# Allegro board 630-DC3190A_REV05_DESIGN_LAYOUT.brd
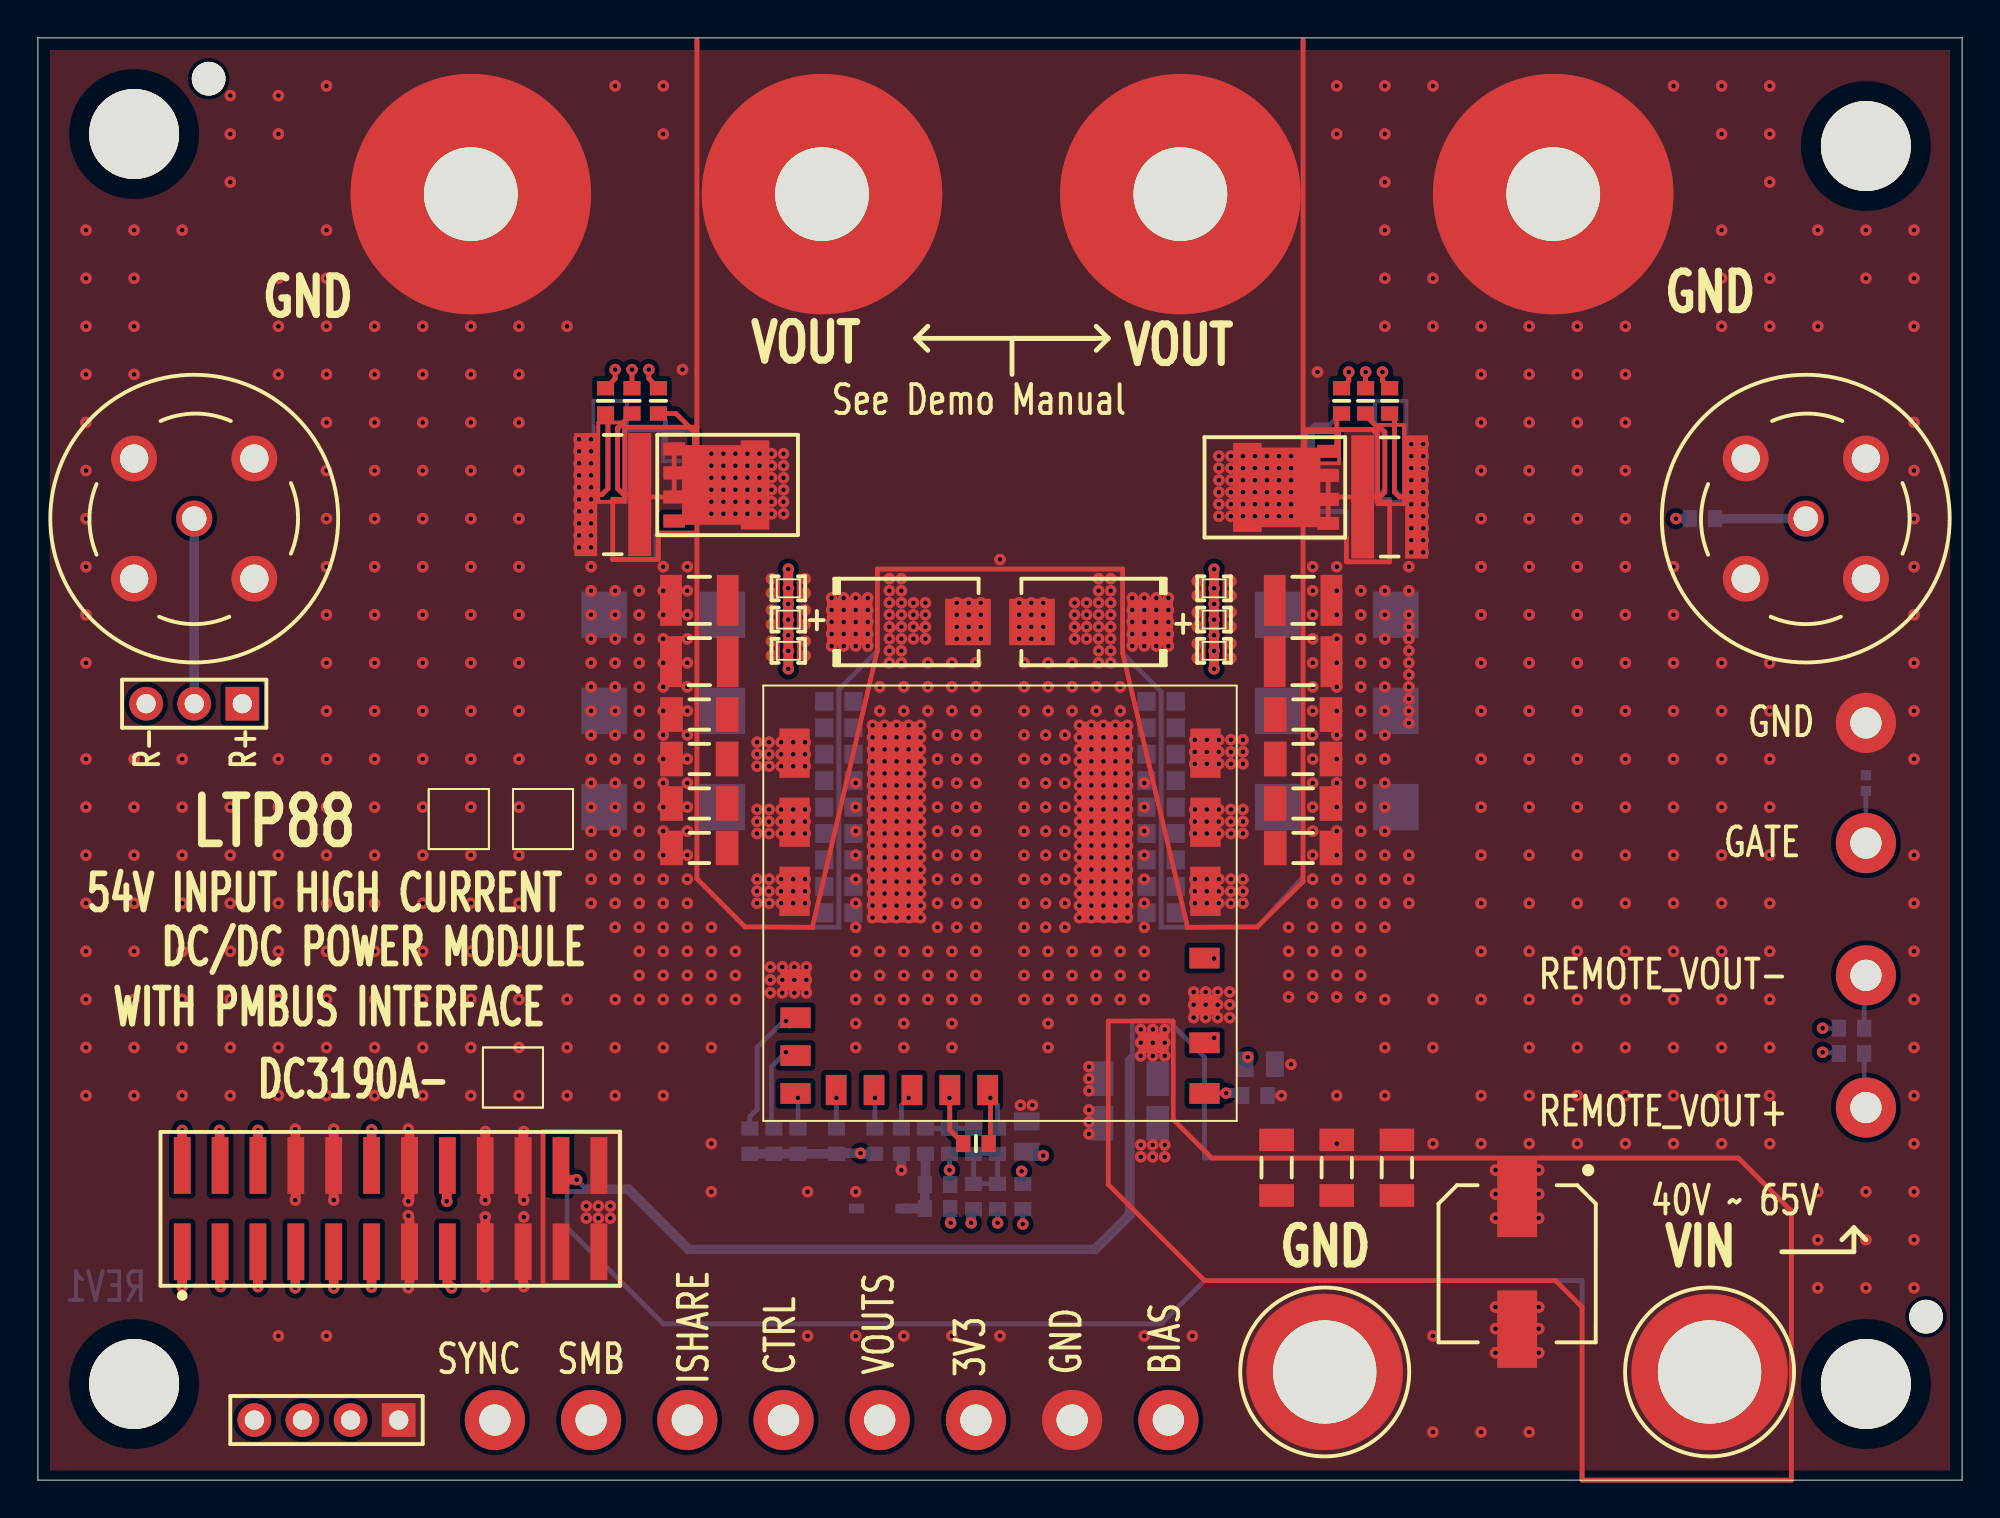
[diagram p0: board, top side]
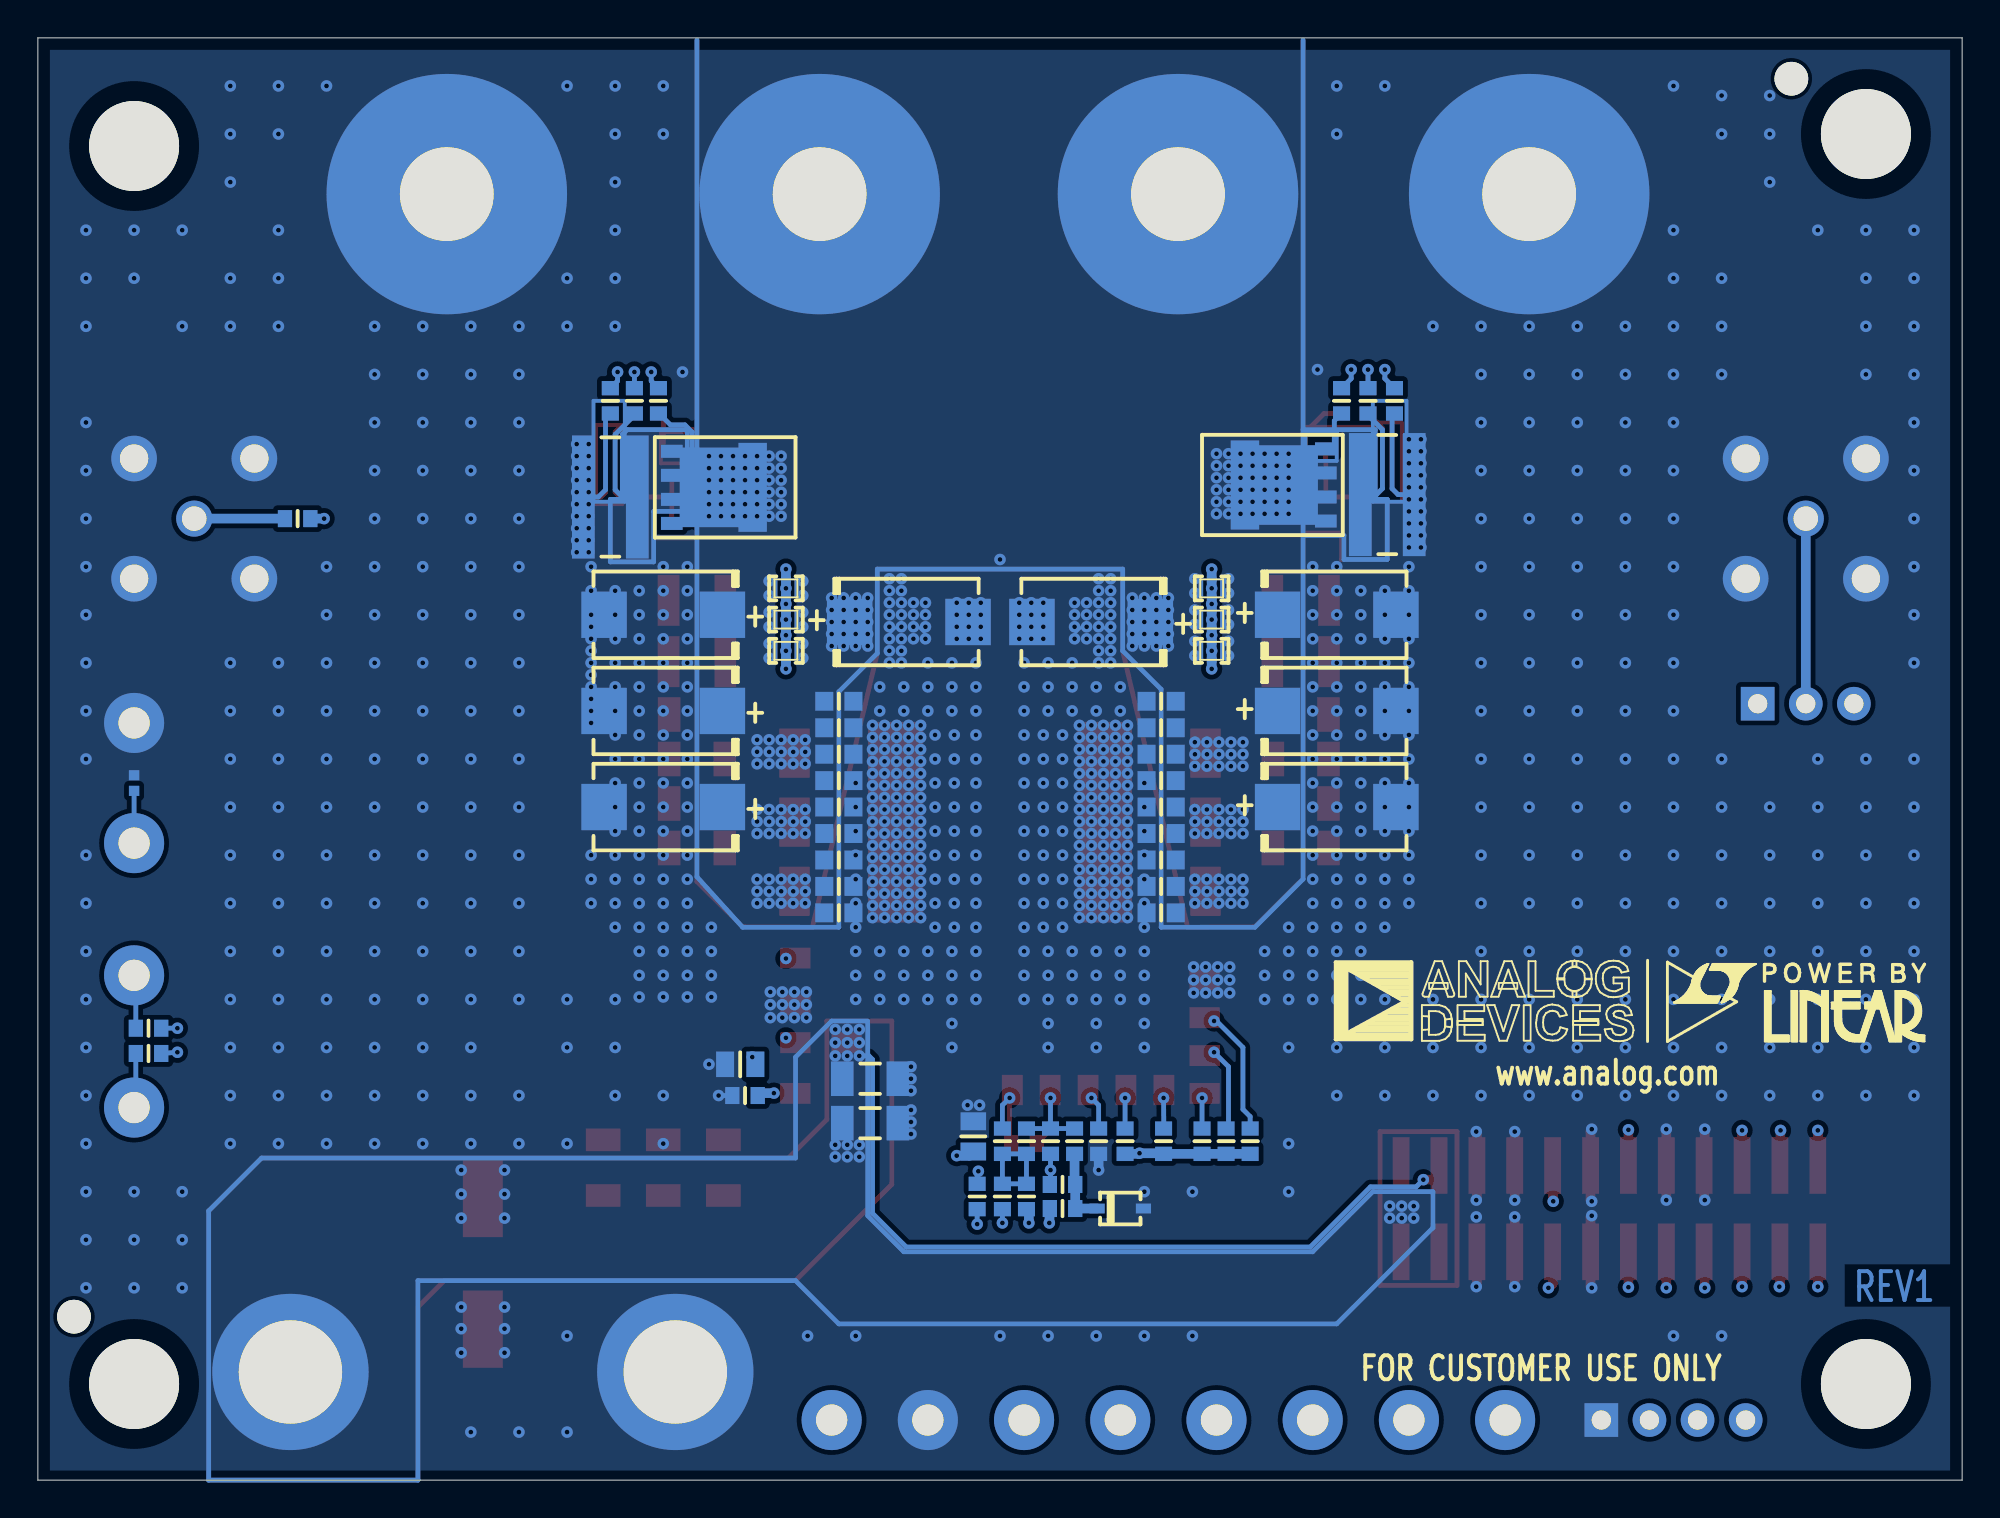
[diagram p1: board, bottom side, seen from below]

Outline 101.6 x 76.2 mm; copper layers: TOP, LAYER2, LAYER3, LAYER4, LAYER5, LAYER6, LAYER7, BOTTOM. Coordinates in mm from the lower left corner of the outline.
Outline path: 0,76.2 0,0 101.6,0 101.6,76.2 0,76.2

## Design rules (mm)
constraint set DEFAULT: min track width 0.254
nets with their own width: min track width 0.127; nets CTRL GND ISHARE LOADGATE N17349827 N17349858 N17349901 N17354471 N17359340 N17393939 N17425885 N173357071 N173562991 N173563321 N174258781 RSENSE+ RSENSE- SCL SDA SMBALERT SYNC VDD VDDEXT VIN VOUT

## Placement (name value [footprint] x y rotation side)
C5  10uF  [CC0603N]  59.31 41.15 180 bottom
C6  10uF  [CC0603N]  42.29 41.15 0 bottom
C7  10uF  [CC0603N]  59.31 39.75 180 bottom
C8  10uF  [CC0603N]  42.29 39.75 0 bottom
C9  10uF  [CC0603N]  59.31 38.35 180 bottom
C10  10uF  [CC0603N]  42.29 38.35 0 bottom
C11  10uF  [CC0603N]  59.31 36.96 180 bottom
C12  10uF  [CC0603N]  42.29 36.96 0 bottom
C13  10uF  [CC0603N]  59.31 35.56 180 bottom
C14  10uF  [CC0603N]  42.29 35.56 0 bottom
C15  10uF  [CC0603N]  59.31 34.16 180 bottom
C16  10uF  [CC0603N]  42.29 34.16 0 bottom
C17  10uF  [CC0603N]  59.31 32.77 180 bottom
C18  10uF  [CC0603N]  42.29 32.77 0 bottom
C19  10uF  [CC0603N]  59.31 31.37 180 bottom
C20  10uF  [CC0603N]  42.29 31.37 0 bottom
C21  10uF  [CC0603N]  59.31 29.97 180 bottom
C22  10uF  [CC0603N]  42.29 29.97 0 bottom
C23  22uF  [MURATA-NFMJMPC]  62.1 47.12 0 top
C24  22uF  [MURATA-NFMJMPC]  62.1 45.47 0 top
C25  22uF  [MURATA-NFMJMPC]  62.1 43.81 0 top
C26  22uF  [MURATA-NFMJMPC]  62.1 45.47 180 bottom
C27  22uF  [MURATA-NFMJMPC]  62.1 43.81 180 bottom
C28  22uF  [MURATA-NFMJMPC]  62.1 47.12 180 bottom
C29  22uF  [MURATA-NFMJMPC]  39.62 47.12 180 bottom
C30  22uF  [MURATA-NFMJMPC]  39.62 45.47 180 bottom
C31  22uF  [MURATA-NFMJMPC]  39.62 43.81 180 bottom
C32  22uF  [MURATA-NFMJMPC]  39.62 47.12 0 top
C33  22uF  [MURATA-NFMJMPC]  39.62 45.47 0 top
C34  22uF  [MURATA-NFMJMPC]  39.62 43.81 0 top
C45  2.2uF  [CC1206N]  57.66 21.21 180 bottom
C46  2.2uF  [CC1206N]  57.66 18.86 180 bottom
C47  22uF  [SUNCON_CE-BS_8X10-2]  78.11 11.43 270 top
C48  10uF  [CC0805L]  64.52 21.97 0 bottom
C49  2.2uF  [CC0805L]  52.21 18.16 90 bottom
C52  100uF  [CC1206N]  34.92 40.45 180 top
C53  100uF  [CC1206N]  66.8 40.45 0 top
C54  100uF  [CC1206N]  34.92 38.1 180 top
C55  100uF  [CC1206N]  66.8 38.1 0 top
C58  100uF  [CC1210N]  34.92 46.48 180 top
C59  100uF  [CC1210N]  66.8 46.48 0 top
C60  100uF  [CC1210N]  34.92 43.24 180 top
C61  100uF  [CC1210N]  66.8 43.24 0 top
C62  OPT  [CC1206N]  34.92 35.75 180 top
C63  OPT  [CC1206N]  66.8 35.75 0 top
C64  OPT  [CC1206N]  34.92 33.4 180 top
C65  OPT  [CC1206N]  66.8 33.4 0 top
C66  150uF  [CAPMP7343N]  55.61 45.34 180 bottom
C67  150uF  [CAPMP7343N]  45.99 45.34 0 bottom
C68  150uF  [CAPMP7343N]  55.61 45.34 180 top
C69  150uF  [CAPMP7343N]  68.58 35.56 0 bottom
C70  150uF  [CAPMP7343N]  68.58 40.64 0 bottom
C71  150uF  [CAPMP7343N]  68.58 45.72 0 bottom
C72  150uF  [CAPMP7343N]  45.99 45.34 0 top
C73  150uF  [CAPMP7343N]  33.02 35.56 180 bottom
C74  150uF  [CAPMP7343N]  33.02 40.64 180 bottom
C75  150uF  [CAPMP7343N]  33.02 45.72 180 bottom
C76  2.2uF  [CC1206N]  65.41 16.51 90 top
C77  2.2uF  [CC1206N]  68.58 16.51 90 top
C78  2.2uF  [CC1206N]  71.75 16.51 90 top
CFF  OPT  [CC0603L]  48.13 17.91 270 bottom
CVS  100pF  [CC0603L]  49.53 17.78 180 top
D1  OPT  [SOD-323L]  44.45 14.35 0 bottom
E3  TEST POINT  [MILLMAX2308]  24.13 3.17 0 top
E4  TEST POINT  [MILLMAX2308]  29.21 3.17 0 top
E5  TEST POINT  [MILLMAX2308]  34.29 3.17 0 top
E6  TEST POINT  [MILLMAX2308]  39.37 3.17 0 top
E7  TEST POINT  [MILLMAX2308]  44.45 3.17 0 top
E8  TEST POINT  [MILLMAX2308]  49.53 3.17 0 top
E9  TEST POINT  [MILLMAX2308]  54.61 3.17 0 top
E10  TEST POINT  [MILLMAX2308]  59.69 3.17 0 top
E11  TEST POINT  [MILLMAX2308]  96.52 33.66 0 top
E12  TEST POINT  [MILLMAX2308]  96.52 40.01 0 top
E13  TEST POINT  [MILLMAX2308]  96.52 19.68 0 top
E14  TEST POINT  [MILLMAX2308]  96.52 26.67 0 top
J1  RF,BNC  [CONNEX-112404]  8.26 50.8 0 top
J2  HDR  [HD1X3-100]  8.26 41.02 180 top
J3  RF,BNC  [CONNEX-112404]  93.34 50.8 0 top
J4  HDR,SHROUDED  [AMPHENOL-69167-104]  19.05 3.17 180 top
J5  SOCKET  [SAMTEC-CLT-112-02-F-D-BE]  7.62 12.06 90 top
J6  STUD,#10-32  [PENN-KFH-032]  60.32 67.94 0 top
J7  STUD,#10-32  [PENN-KFH-032]  41.4 67.94 0 top
J8  STUD,#10-32  [PENN-KFH-032]  80.01 67.94 0 top
J9  STUD,#10-32  [PENN-KFH-032]  22.86 67.94 0 top
J10  BANANA JACK  [KEY-575-4]  88.27 5.71 0 top
J11  BANANA JACK  [KEY-575-4]  67.94 5.71 0 top
M1  PSMN5R4-25YLDX  [NXP-LFPAK56]  36.32 52.58 270 top
M2  PSMN5R4-25YLDX  [NXP-LFPAK56]  65.41 52.45 270 bottom
M3  PSMN5R4-25YLDX  [NXP-LFPAK56]  36.32 52.58 90 bottom
M4  PSMN5R4-25YLDX  [NXP-LFPAK56]  65.41 52.45 90 top
NOREF  -  []  0 0 90 top
NOREF#2  -  [unnamed#2]  99.69 8.64 0 top
NOREF#3  -  [unnamed#2]  5.08 5.08 0 top
NOREF#4  -  [unnamed#2]  96.52 70.48 0 top
NOREF#5  -  [unnamed#2]  5.08 71.12 0 top
NOREF#6  -  [unnamed#2]  96.52 5.08 0 top
NOREF#7  -  [unnamed#2]  9.02 74.04 0 top
NOREF#8  -  []  0 0 0 top
R1  24.9  [CR0603L]  32.77 57.02 270 top
R2  24.9  [CR0603L]  68.83 57.02 270 bottom
R3  24.9  [CR0603L]  32.77 57.02 270 bottom
R4  24.9  [CR0603L]  68.83 57.02 270 top
R5  200  [CR0603L]  70.1 57.02 90 bottom
R6  200  [CR0603L]  70.1 57.02 90 top
R7  200  [CR0603L]  31.37 57.02 90 top
R8  200  [CR0603L]  31.37 57.02 90 bottom
R9  0.006  [SUSUMU-KRL6432]  71.37 51.94 0 bottom
R10  0.006  [SUSUMU-KRL6432]  71.37 51.94 0 top
R11  0.006  [SUSUMU-KRL6432]  30.35 52.07 180 top
R12  0.006  [SUSUMU-KRL6432]  30.35 52.07 180 bottom
R13  200  [CR0603L]  71.37 57.02 90 bottom
R14  200  [CR0603L]  71.37 57.02 90 top
R15  200  [CR0603L]  29.97 57.02 90 top
R16  200  [CR0603L]  29.97 57.02 90 bottom
R17  49.9  [CR0603L]  87.88 50.8 0 bottom
R18  4.99k  [CR0603L]  37.59 17.91 270 bottom
R19  4.99k  [CR0603L]  38.86 17.91 270 bottom
R20  4.99k  [CR0603L]  40.13 17.91 270 bottom
R21  4.99k  [CR0603L]  44.2 17.91 270 bottom
R22  4.99k  [CR0603L]  42.16 17.91 270 bottom
R25  750  [CR0603L]  45.59 17.91 270 bottom
R26  10k  [CR0603L]  64.26 20.32 0 bottom
R27  10k  [CR0402L]  96.52 36.83 90 bottom
R31  1.21k  [CR0603L]  46.86 17.91 270 bottom
R32  2k  [CR0603L]  49.4 17.91 270 bottom
R33  7.5  [CR0603L]  50.67 17.91 90 bottom
R34  OPT  [CR0603L]  47.5 15.62 0 bottom
R37  OPT  [CR0603L]  50.67 14.99 270 bottom
R38  OPT  [CR0603L]  95.76 22.54 0 bottom
R39  OPT  [CR0603L]  95.76 23.88 0 bottom
RFF  OPT  [CR0603L]  52.01 14.99 270 bottom
RSN  0  [CR0603L]  49.4 14.99 270 bottom
RSP  1  [CR0603L]  47.5 14.35 0 bottom
U1  -  [LTP8800]  50.8 30.48 90 top

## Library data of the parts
C5-C22 C45 C46 C48 C49 C52-C55 C58-C65 C76-C78 CFF CVS = CAP
C23-C34 = CAP-4PIN
C47 = CAP_P_ALT
C66-C75 = CAP_P
D1 = DIODE_SCHOTTKY_A_ALT
E3-E14 = TEST_POINT_.156_MILL-MAX_2308_A
J1 J3 = BNC_50_OHM_112404_C
J2 = HDR1X3_ALT1
J4 = HDR1X4_ALT1
J5 = HDR2X12
J6-J9 = PEM-KFH
J10 J11 = BANANA_KEYSTONE-575-4
M1-M4 = 5P_N-CH_TYPE1C_1
R1-R22 R25-R27 R31-R34 R37-R39 RFF RSN RSP = RES
U1 = LTP8800

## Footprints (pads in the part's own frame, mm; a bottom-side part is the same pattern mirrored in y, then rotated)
AMPHENOL-69167-104
  rect 1.778x1.778 hole 1.016: 1(0,0)
  round 1.778 hole 1.016: 2(2.54,0) 3(5.08,0) 4(7.62,0)
CAPMP7343N
  rect 2.4x2.45 smd: 1(-3.125,0) 2(3.125,0)
CC0603L
  rect 0.755x0.9 smd: 1(-0.67,0) 2(0.67,0)
CC0603N
  rect 0.955x1 smd: 1(-0.77,0) 2(0.77,0)
CC0805L
  rect 0.95x1.35 smd: 1(-0.799,0) 2(0.799,0)
CC1206N
  rect 1.195x1.83 smd: 1(-1.469,0) 2(1.469,0)
CC1210N
  rect 1.15x2.69 smd: 1(-1.496,0) 2(1.496,0)
CONNEX-112404
  round 1.905 hole 1.295: 1(0,0)
  round 2.413 hole 1.499: 2(-3.175,3.175) 3(3.175,3.175) 4(3.175,-3.175) 5(-3.175,-3.175)
CR0402L
  rect 0.535x0.55 smd: 1(-0.414,0) 2(0.414,0)
CR0603L
  rect 0.755x0.9 smd: 1(-0.67,0) 2(0.67,0)
HD1X3-100
  rect 1.778x1.778 hole 1.016: 1(-2.54,0)
  round 1.778 hole 1.016: 2(0,0) 3(2.54,0)
KEY-575-4
  round 8.255 hole 5.461: 1(0,0)
LTP8800
  rect 1.1x1.6 smd: 1(-10.05,10.8) 7(-10.05,-10.8) 8(-7.37,-10.8) 9(-5.37,-10.8) 10(-2.9,-10.8) 19(-4.05,10.8) 20(-6.05,10.8) 21(-8.05,10.8) 22(-7.37,-8.1)
  rect 1.6x1.1 smd: 2(-9.87,8.65) 3(-9.87,6.65) 4(-9.87,4.65) 5(-9.87,2.65) 6(-9.87,0.65)
  rect 2.601x1.6 smd: 11(0.63,-10.85) 12(4.28,-10.85) 13(7.93,-10.85) 16(7.93,10.85) 17(4.28,10.85) 18(0.63,10.85)
  rect 10.604x2.896 smd: 14(4.28,-5.52) 15(4.28,5.52)
MILLMAX2308
  round 3.175 hole 1.651: 1(0,0)
MURATA-NFMJMPC
  rect 0.249x0.899 smd: 1(-0.575,0) 3(0.575,0)
  rect 0.5x0.325 smd: 2(0,0.475) 4(0,-0.475)
NXP-LFPAK56
  rect 0.686x1.143 smd: 1(-1.905,-2.725) 2(-0.635,-2.725) 3(0.635,-2.725) 4(1.905,-2.725)
  custom 1.15x1.15 smd: 5(-0.003,-0.005)
PENN-KFH-032
  round 12.7 hole 4.953: 1(0,0)
SAMTEC-CLT-112-02-F-D-BE
  rect 2.997x0.889 smd: 1(0,0) 2(4.559,0) 3(0,-2) 4(4.559,-2) 5(0,-4) 6(4.559,-4) 7(0,-6) 8(4.559,-6) 9(0,-8) 10(4.559,-8) 11(0,-10) 12(4.559,-10) 13(0,-12) 14(4.559,-12) 15(0,-14) 16(4.559,-14) 17(0,-16) 18(4.559,-16) 19(0,-18) 20(4.559,-18) 21(0,-20) 22(4.559,-20) 23(0,-22) 24(4.559,-22)
SOD-323L
  rect 0.805x0.52 smd: 1(1.223,0) 2(-1.223,0)
SUNCON_CE-BS_8X10-2
  rect 4.089x2.108 smd: 1(-3.454,0) 2(3.454,0)
SUSUMU-KRL6432
  rect 1.2x6.5 smd: 1(-1.424,0) 2(1.424,0)
unnamed#2
  round 1.778 hole 1.778 unplated: (0,0)

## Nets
GND: C5.2 C6.2 C7.2 C8.2 C9.2 C10.2 C11.2 C12.2 C13.2 C14.2 C15.2 C16.2 C17.2 C18.2 C19.2 C20.2 C21.2 C22.2 C23.2 C23.4 C24.2 C24.4 C25.2 C25.4 C26.2 C26.4 C27.2 C27.4 C28.2 C28.4 C29.2 C29.4 C30.2 C30.4 C31.2 C31.4 C32.2 C32.4 C33.2 C33.4 C34.2 C34.4 C45.2 C46.2 C47.2 C48.2 C49.2 C52.2 C53.2 C54.2 C55.2 C58.2 C59.2 C60.2 C61.2 C62.2 C63.2 C64.2 C65.2 C66.2 C67.2 C68.2 C69.2 C70.2 C71.2 C72.2 C73.2 C74.2 C75.2 C76.2 C77.2 C78.2 D1.2 E9.1 E12.1 J1.2 J1.3 J1.4 J1.5 J3.2 J3.3 J3.4 J3.5 J4.1 J5.8 J5.10 J5.13 J5.14 J5.17 J5.18 J5.19 J5.20 J8.1 J9.1 J11.1 R9.2 R10.2 R11.2 R12.2 R13.1 R14.1 R15.1 R16.1 R25.2 R26.2 R27.2 RSN.2 U1.9 U1.14 U1.15 U1.19
VDD: C49.1 E8.1 J5.16 R18.2 R19.2 R20.2 R21.2 R22.2 U1.8
VDDEXT: C48.1 E10.1 J5.15 U1.10
VIN: C45.1 C46.1 C47.1 C76.1 C77.1 C78.1 J5.21 J5.22 J5.23 J5.24 J10.1 U1.22
CTRL: E6.1 J5.11 R21.1 U1.3
ISHARE: E5.1 J5.9 R22.1 U1.2
LOADGATE: E11.1 J5.6 R1.1 R2.1 R3.1 R4.1 R27.1
RSENSE+: J2.1 J5.4 R5.2 R6.2 R7.2 R8.2
RSENSE-: J2.3 J5.2 R13.2 R14.2 R15.2 R16.2
SCL: J4.3 J5.5 R18.1 U1.20
SDA: J4.2 J5.3 R19.1 U1.21
SMBALERT: E4.1 J5.7 R20.1 U1.1
SYNC: E3.1 J5.1 R26.1 U1.7
VOUT: C5.1 C6.1 C7.1 C8.1 C9.1 C10.1 C11.1 C12.1 C13.1 C14.1 C15.1 C16.1 C17.1 C18.1 C19.1 C20.1 C21.1 C22.1 C23.1 C23.3 C24.1 C24.3 C25.1 C25.3 C26.1 C26.3 C27.1 C27.3 C28.1 C28.3 C29.1 C29.3 C30.1 C30.3 C31.1 C31.3 C32.1 C32.3 C33.1 C33.3 C34.1 C34.3 C52.1 C53.1 C54.1 C55.1 C58.1 C59.1 C60.1 C61.1 C62.1 C63.1 C64.1 C65.1 C66.1 C67.1 C68.1 C69.1 C70.1 C71.1 C72.1 C73.1 C74.1 C75.1 E7.1 J5.12 J6.1 J7.1 M1.5 M2.5 M3.5 M4.5 R17.1 RSP.2 U1.11 U1.12 U1.13 U1.16 U1.17 U1.18
N17349827: M4.1 M4.2 M4.3(S3) R6.1 R10.1
N17349858: M1.1 M1.2 M1.3(S3) R7.1 R11.1
N17349901: M2.1 M2.2 M2.3(S3) R5.1 R9.1
N17354471: M4.4 R4.2
N17359340: J1.1 J2.2
N17393939: R25.1 U1.4
N17425885: M3.1 M3.2 M3.3(S3) R8.1 R12.1
N17521903: R38.1 RFF.2
N17521912: R37.2 R39.1
N17523958: CVS.1 R33.2 U1.6(VS-)
N17523961: CFF.1 CVS.2 R31.1 R32.1 U1.5
N17524029: R32.2 R33.1 R37.1 RSN.1
N17524083: D1.1(C) R31.2 R34.1 RSP.1
N17524971: CFF.2 R34.2 RFF.1
N173357071: J3.1 R17.2
N173562991: M1.4 R1.2
N173563321: M2.4 R2.2
N174258781: M3.4 R3.2
N175287170: E13.1 R38.2
N175287240: E14.1 R39.2

Pads without a net: J4 4

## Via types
v1: diameter 0.61, hole 0.254, TOP to BOTTOM, 414 vias
v2: diameter 0.61, hole 0.249, TOP to BOTTOM, 917 vias

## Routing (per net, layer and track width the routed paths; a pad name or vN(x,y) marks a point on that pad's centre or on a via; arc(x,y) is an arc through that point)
GND: length 117.7
  TOP w0.127: 55.37,45.34 54.74,44.7 ; 46.23,45.34 46.86,44.7 ; 56.01,45.34 56.64,44.7 ; 45.59,45.34 44.96,44.7 ; 52.45,45.34 53.09,44.7 ; 49.15,45.34 48.51,44.7
  TOP w0.254: R11.2 29.78,52.07 30.1,52.39 30.1,56.23 R15.1 ; R14.1 71.63,56.1 71.63,52.2 71.88,51.94 R10.2
  TOP w0.508: v1(19.56,10.16) 19.62,10.22 J5.13 19.62,13.91 v1(19.56,13.97) ; v1(25.65,18.41) 25.62,18.38 J5.20 25.62,14.83 v1(25.65,14.8) ; v1(15.62,18.54) 15.62,18.41 J5.10 v1(15.62,14.8) ; v2(39.62,48.13) C32.2 v2(39.62,47.12) C32.4 39.62,46.39 ; v2(62.1,48.13) C23.2 v2(62.1,47.12) C23.4 v2(62.1,46.29) C24.2 v2(62.1,45.47) C24.4 v2(62.1,44.64) C25.2 v2(62.1,43.81) C25.4 v2(62.1,42.86) ; v2(39.62,46.29) C33.2 v2(39.62,45.47) C33.4 v2(39.62,44.64) C34.2 v2(39.62,43.81) C34.4 v2(39.62,42.86) ; v1(19.56,14.73) 19.62,14.8 J5.14 19.62,18.41 v1(19.56,18.54) ; v1(13.59,14.8) 13.62,14.83 J5.8 v1(13.59,18.54) ; J5.19 25.62,10.26 v1(25.65,10.22) ; v1(23.62,18.41) 23.62,18.41 J5.18 23.62,14.8 v1(23.62,14.8) ; v1(23.62,10.22) 23.62,10.23 J5.17 23.62,13.9 v1(23.62,13.91)
  LAYER5 w0.254: v2(51.82,44.45) 51.31,43.94 51.31,23.54 49.53,21.76 49.53,15.11 49.02,14.61 49.02,13.84 v1(49.28,13.59)
  LAYER5 w0.635: v2(52.45,44.45) v2(51.82,44.45) v2(51.82,45.09)
  BOTTOM w0.127: 45.59,45.34 44.96,44.7 ; 52.45,45.34 53.09,44.7 ; 56.01,45.34 56.64,44.7 ; 46.23,45.34 46.86,44.7 ; 49.15,45.34 48.51,44.7 ; 55.37,45.34 54.74,44.7
  BOTTOM w0.254: 56.14,20.7 55.37,20.7 ; R14.1 71.63,56.1 71.63,52.32 72.01,51.94 R10.2 ; R11.2 29.78,52.07 30.1,52.39 30.1,56.23 R15.1 ; R26.2 v2(65.66,20.32)
  BOTTOM w0.508: R25.2 v1(45.59,16.38) ; v2(39.62,42.86) C34.4 v2(39.62,43.81) C34.2 v2(39.62,44.64) C33.4 v2(39.62,45.47) C33.2 v2(39.62,46.29) C32.4 v2(39.62,47.12) C32.2 v2(39.62,48.13) ; RSN.2 49.28,14.19 v1(49.28,13.59) ; v2(62.1,48.13) C23.2 v2(62.1,47.12) C23.4 v2(62.1,46.29) C24.2 v2(62.1,45.47) C24.4 v2(62.1,44.64) C25.2 v2(62.1,43.81) C25.4 62.1,43.09
  vias: v1(2.54,66.04) v1(2.54,63.5) v1(2.54,60.96) v1(2.54,58.42) v1(2.54,55.88) v1(2.54,53.34) v1(2.54,50.8) v1(2.54,48.26) v1(2.54,45.72) v1(2.54,43.18) v1(2.54,38.1) v1(2.54,35.56) v1(2.54,33.02) v1(2.54,30.48) v1(2.54,27.94) v1(2.54,25.4) v1(2.54,22.86) v1(2.54,20.32) v1(5.08,66.04) v1(5.08,63.5) v1(5.08,60.96) v1(5.08,58.42) v1(5.08,38.1) v1(5.08,35.56) v1(5.08,33.02) v1(5.08,30.48) v1(5.08,27.94) v1(5.08,25.4) v1(5.08,22.86) v1(5.08,20.32) v1(7.62,66.04) v1(7.62,38.1) v1(7.62,35.56) v1(7.62,33.02) v1(7.62,30.48) v1(7.62,27.94) v1(7.62,25.4) v1(7.62,22.86) v1(7.62,20.32) v1(10.16,73.15) v1(10.16,71.12) v1(10.16,68.58) v1(10.16,35.56) v1(10.16,33.02) v1(10.16,30.48) v1(10.16,27.94) v1(10.16,25.4) v1(10.16,22.86) v1(10.16,20.32) v1(12.7,73.15) v1(12.7,71.12) v1(12.7,63.5) v1(12.7,60.96) v1(12.7,58.42) v1(12.7,38.1) v1(12.7,35.56) v1(12.7,33.02) v1(12.7,30.48) v1(12.7,27.94) v1(12.7,25.4) v1(12.7,22.86) v1(12.7,20.32) v1(12.7,7.62) v1(15.24,73.66) v1(15.24,66.04) v1(15.24,63.5) v1(15.24,60.96) v1(15.24,58.42) v1(15.24,55.88) v1(15.24,53.34) v1(15.24,50.8) v1(15.24,48.26) v1(15.24,45.72) v1(15.24,43.18) v1(15.24,40.64) v1(15.24,38.1) v1(15.24,35.56) v1(15.24,33.02) v1(15.24,30.48) v1(15.24,27.94) v1(15.24,25.4) v1(15.24,22.86) v1(15.24,20.32) v1(15.24,7.62) v1(17.78,60.96) v1(17.78,58.42) v1(17.78,55.88) v1(17.78,53.34) v1(17.78,50.8) v1(17.78,48.26) v1(17.78,45.72) v1(17.78,43.18) v1(17.78,40.64) v1(17.78,38.1) v1(17.78,35.56) v1(17.78,33.02) v1(17.78,30.48) v1(17.78,27.94) v1(17.78,25.4) v1(17.78,22.86) v1(17.78,20.32) v1(20.32,60.96) v1(20.32,58.42) v1(20.32,55.88) v1(20.32,53.34) v1(20.32,50.8) v1(20.32,48.26) v1(20.32,45.72) v1(20.32,43.18) v1(20.32,40.64) v1(20.32,38.1) v1(20.32,35.56) v1(20.32,33.02) v1(20.32,30.48) v1(20.32,27.94) v1(20.32,25.4) v1(20.32,22.86) v1(20.32,20.32) v1(22.86,60.96) v1(22.86,58.42) v1(22.86,55.88) v1(22.86,53.34) v1(22.86,50.8) v1(22.86,48.26) v1(22.86,45.72) v1(22.86,43.18) v1(22.86,40.64) v1(22.86,38.1) v1(22.86,35.56) v1(22.86,33.02) v1(22.86,30.48) v1(22.86,27.94) v1(22.86,25.4) v1(22.86,22.86) v1(22.86,20.32) v1(25.4,60.96) v1(25.4,58.42) v1(25.4,55.88) v1(25.4,53.34) v1(25.4,50.8) v1(25.4,48.26) v1(25.4,45.72) v1(25.4,43.18) v1(25.4,40.64) v1(25.4,38.1) v1(25.4,35.56) v1(25.4,33.02) v1(25.4,30.48) v1(25.4,27.94) v1(25.4,25.4) v1(25.4,22.86) v1(25.4,20.32) v1(25.65,13.91) v1(27.94,60.96) v1(27.94,25.4) v1(27.94,22.86) v1(27.94,20.32) v1(30.48,73.66) v1(30.48,25.4) v1(30.48,22.86) v1(30.48,20.32) v1(33.02,73.66) v1(33.02,71.12) v1(33.02,22.86) v1(33.02,20.32) v1(34.04,58.67) v1(35.56,22.86) v1(35.56,17.78) v1(35.56,15.24) v1(40.64,15.24) v1(40.64,7.62) v1(43.18,15.24) v1(43.18,7.62) v1(45.72,7.62) v1(48.26,7.62) v1(50.8,7.62) v1(58.42,7.62) v1(60.96,7.62) v1(67.56,58.55) v1(68.58,73.66) v1(68.58,71.12) v1(68.58,20.32) v1(68.58,17.78) v1(71.12,73.66) v1(71.12,71.12) v1(71.12,68.58) v1(71.12,66.04) v1(71.12,63.5) v1(71.12,60.96) v1(71.12,25.4) v1(71.12,22.86) v1(71.12,20.32) v1(73.66,73.66) v1(73.66,63.5) v1(73.66,60.96) v1(73.66,25.4) v1(73.66,22.86) v1(73.66,17.78) v1(73.66,7.62) v1(73.66,2.54) v1(76.2,60.96) v1(76.2,58.42) v1(76.2,55.88) v1(76.2,53.34) v1(76.2,50.8) v1(76.2,48.26) v1(76.2,45.72) v1(76.2,43.18) v1(76.2,40.64) v1(76.2,38.1) v1(76.2,35.56) v1(76.2,33.02) v1(76.2,30.48) v1(76.2,27.94) v1(76.2,25.4) v1(76.2,20.32) v1(76.2,17.78) v1(76.2,2.54) v1(76.96,9.14) v1(76.96,8) v1(76.96,6.73) v1(78.74,60.96) v1(78.74,58.42) v1(78.74,55.88) v1(78.74,53.34) v1(78.74,50.8) v1(78.74,48.26) v1(78.74,45.72) v1(78.74,43.18) v1(78.74,40.64) v1(78.74,38.1) v1(78.74,35.56) v1(78.74,33.02) v1(78.74,30.48) v1(78.74,27.94) v1(78.74,25.4) v1(78.74,22.86) v1(78.74,20.32) v1(78.74,17.78) v1(78.74,2.54) v1(79.25,9.14) v1(79.25,8) v1(79.25,6.73) v1(81.28,60.96) v1(81.28,58.42) v1(81.28,55.88) v1(81.28,53.34) v1(81.28,50.8) v1(81.28,48.26) v1(81.28,45.72) v1(81.28,43.18) v1(81.28,40.64) v1(81.28,38.1) v1(81.28,35.56) v1(81.28,33.02) v1(81.28,30.48) v1(81.28,27.94) v1(81.28,25.4) v1(81.28,22.86) v1(81.28,20.32) v1(81.28,17.78) v1(83.82,60.96) v1(83.82,58.42) v1(83.82,55.88) v1(83.82,53.34) v1(83.82,50.8) v1(83.82,48.26) v1(83.82,45.72) v1(83.82,43.18) v1(83.82,40.64) v1(83.82,38.1) v1(83.82,35.56) v1(83.82,33.02) v1(83.82,30.48) v1(83.82,27.94) v1(83.82,25.4) v1(83.82,22.86) v1(83.82,20.32) v1(83.82,17.78) v1(86.36,73.66) v1(86.36,48.26) v1(86.36,45.72) v1(86.36,43.18) v1(86.36,40.64) v1(86.36,38.1) v1(86.36,35.56) v1(86.36,33.02) v1(86.36,30.48) v1(86.36,27.94) v1(86.36,25.4) v1(86.36,22.86) v1(86.36,20.32) v1(86.36,17.78) v1(88.9,73.66) v1(88.9,71.12) v1(88.9,66.04) v1(88.9,63.5) v1(88.9,60.96) v1(88.9,43.18) v1(88.9,40.64) v1(88.9,38.1) v1(88.9,35.56) v1(88.9,33.02) v1(88.9,30.48) v1(88.9,27.94) v1(88.9,25.4) v1(88.9,22.86) v1(88.9,20.32) v1(88.9,17.78) v1(91.44,73.66) v1(91.44,71.12) v1(91.44,68.58) v1(91.44,63.5) v1(91.44,60.96) v1(91.44,43.18) v1(91.44,40.64) v1(91.44,38.1) v1(91.44,35.56) v1(91.44,33.02) v1(91.44,30.48) v1(91.44,27.94) v1(91.44,25.4) v1(91.44,22.86) v1(91.44,20.32) v1(91.44,17.78) v1(93.98,66.04) v1(93.98,60.96) v1(93.98,15.24) v1(93.98,12.7) v1(93.98,10.16) v1(96.52,66.04) v1(96.52,63.5) v1(96.52,15.24) v1(96.52,12.7) v1(96.52,10.16) v1(99.06,66.04) v1(99.06,63.5) v1(99.06,60.96) v1(99.06,55.88) v1(99.06,53.34) v1(99.06,50.8) v1(99.06,48.26) v1(99.06,45.72) v1(99.06,43.18) v1(99.06,40.64) v1(99.06,38.1) v1(99.06,33.02) v1(99.06,30.48) v1(99.06,27.94) v1(99.06,25.4) v1(99.06,22.86) v1(99.06,20.32) v1(99.06,17.78) v1(99.06,15.24) v1(99.06,12.7) v1(99.06,10.16) v2(28.57,54.99) v2(28.57,54.36) v2(28.57,53.72) v2(28.57,53.09) v2(28.57,52.45) v2(28.57,51.82) v2(28.57,51.18) v2(28.57,50.55) v2(28.57,49.91) v2(28.57,49.28) v2(29.21,54.99) v2(29.21,54.36) v2(29.21,53.72) v2(29.21,53.09) v2(29.21,52.45) v2(29.21,51.82) v2(29.21,51.18) v2(29.21,50.55) v2(29.21,49.91) v2(29.21,49.28) v2(29.21,48.26) v2(29.21,46.99) v2(29.21,45.72) v2(29.21,44.45) v2(29.21,43.18) v2(29.21,41.91) v2(29.21,40.64) v2(29.21,39.37) v2(29.21,38.1) v2(29.21,36.83) v2(29.21,35.56) v2(29.21,34.29) v2(29.21,33.02) v2(29.21,31.75) v2(29.21,30.48) v2(30.48,46.99) v2(30.48,45.72) v2(30.48,44.45) v2(30.48,43.18) v2(30.48,41.91) v2(30.48,40.64) v2(30.48,39.37) v2(30.48,38.1) v2(30.48,36.83) v2(30.48,35.56) v2(30.48,34.29) v2(30.48,33.02) v2(30.48,31.75) v2(30.48,30.48) v2(30.48,29.21) v2(31.75,46.99) v2(31.75,45.72) v2(31.75,44.45) v2(31.75,43.18) v2(31.75,41.91) v2(31.75,40.64) v2(31.75,39.37) v2(31.75,38.1) v2(31.75,36.83) v2(31.75,35.56) v2(31.75,34.29) v2(31.75,33.02) v2(31.75,31.75) v2(31.75,30.48) v2(31.75,29.21) v2(31.75,27.94) v2(31.75,26.67) v2(31.75,25.4) v2(33.02,48.26) v2(33.02,46.99) v2(33.02,45.72) v2(33.02,44.45) v2(33.02,43.18) v2(33.02,41.91) v2(33.02,40.64) v2(33.02,39.37) v2(33.02,38.1) v2(33.02,36.83) v2(33.02,35.56) v2(33.02,34.29) v2(33.02,33.02) v2(33.02,31.75) v2(33.02,30.48) v2(33.02,29.21) v2(33.02,27.94) v2(33.02,26.67) v2(33.02,25.4) v2(34.29,48.26) v2(34.29,46.99) v2(34.29,45.72) v2(34.29,44.45) v2(34.29,43.18) v2(34.29,41.91) v2(34.29,40.64) v2(34.29,39.37) v2(34.29,38.1) v2(34.29,36.83) v2(34.29,35.56) v2(34.29,34.29) v2(34.29,33.02) v2(34.29,31.75) v2(34.29,30.48) v2(34.29,29.21) v2(34.29,27.94) v2(34.29,26.67) v2(34.29,25.4) v2(35.56,29.21) v2(35.56,27.94) v2(35.56,26.67) v2(35.56,25.4) v2(36.83,27.94) v2(36.83,26.67) v2(36.83,25.4) v2(38.67,27.11) v2(38.67,26.43) v2(38.67,25.74) v2(39.31,27.11) v2(39.31,26.43) v2(39.31,25.74) v2(39.94,27.11) v2(39.94,26.43) v2(39.94,25.74) v2(40.58,27.11) v2(40.58,26.43) v2(40.58,25.74) v2(43.18,36.83) v2(43.18,35.56) v2(43.18,34.29) v2(43.18,33.02) v2(43.18,31.75) v2(43.18,30.48) v2(43.18,29.21) v2(43.18,27.94) v2(43.18,26.67) v2(43.18,25.4) v2(43.18,24.13) v2(43.18,22.86) v2(44.07,39.88) v2(44.07,39.24) v2(44.07,38.61) v2(44.07,37.97) v2(44.07,37.34) v2(44.07,36.7) v2(44.07,36.07) v2(44.07,35.43) v2(44.07,34.8) v2(44.07,34.16) v2(44.07,33.53) v2(44.07,32.89) v2(44.07,32.26) v2(44.07,31.62) v2(44.07,30.99) v2(44.07,30.35) v2(44.07,29.72) v2(44.45,41.91) v2(44.45,40.64) v2(44.45,27.94) v2(44.45,26.67) v2(44.45,25.4) v2(44.7,39.88) v2(44.7,39.24) v2(44.7,38.61) v2(44.7,37.97) v2(44.7,37.34) v2(44.7,36.7) v2(44.7,36.07) v2(44.7,35.43) v2(44.7,34.8) v2(44.7,34.16) v2(44.7,33.53) v2(44.7,32.89) v2(44.7,32.26) v2(44.7,31.62) v2(44.7,30.99) v2(44.7,30.35) v2(44.7,29.72) v2(44.96,47.62) v2(44.96,46.99) v2(44.96,46.35) v2(44.96,45.72) v2(44.96,45.09) v2(44.96,44.45) v2(44.96,43.81) v2(44.96,43.18) v2(45.34,39.88) v2(45.34,39.24) v2(45.34,38.61) v2(45.34,37.97) v2(45.34,37.34) v2(45.34,36.7) v2(45.34,36.07) v2(45.34,35.43) v2(45.34,34.8) v2(45.34,34.16) v2(45.34,33.53) v2(45.34,32.89) v2(45.34,32.26) v2(45.34,31.62) v2(45.34,30.99) v2(45.34,30.35) v2(45.34,29.72) v2(45.59,47.62) v2(45.59,46.99) v2(45.59,46.35) v2(45.59,45.72) v2(45.59,45.09) v2(45.59,44.45) v2(45.59,43.81) v2(45.59,43.18) v2(45.72,41.91) v2(45.72,40.64) v2(45.72,27.94) v2(45.72,26.67) v2(45.72,25.4) v2(45.72,24.13) v2(45.72,22.86) v2(45.97,39.88) v2(45.97,39.24) v2(45.97,38.61) v2(45.97,37.97) v2(45.97,37.34) v2(45.97,36.7) v2(45.97,36.07) v2(45.97,35.43) v2(45.97,34.8) v2(45.97,34.16) v2(45.97,33.53) v2(45.97,32.89) v2(45.97,32.26) v2(45.97,31.62) v2(45.97,30.99) v2(45.97,30.35) v2(45.97,29.72) v2(46.23,46.35) v2(46.23,45.72) v2(46.23,45.09) v2(46.23,44.45) v2(46.61,39.88) v2(46.61,39.24) v2(46.61,38.61) v2(46.61,37.97) v2(46.61,37.34) v2(46.61,36.7) v2(46.61,36.07) v2(46.61,35.43) v2(46.61,34.8) v2(46.61,34.16) v2(46.61,33.53) v2(46.61,32.89) v2(46.61,32.26) v2(46.61,31.62) v2(46.61,30.99) v2(46.61,30.35) v2(46.61,29.72) v2(46.86,46.35) v2(46.86,45.72) v2(46.86,45.09) v2(46.86,44.45) v2(46.99,43.18) v2(46.99,41.91) v2(46.99,40.64) v2(46.99,27.94) v2(46.99,26.67) v2(46.99,25.4) v2(47.5,39.37) v2(47.5,38.1) v2(47.5,36.83) v2(47.5,35.56) v2(47.5,34.29) v2(47.5,33.02) v2(47.5,31.75) v2(47.5,30.48) v2(47.5,29.21) v2(48.26,43.18) v2(48.26,41.91) v2(48.26,40.64) v2(48.26,27.94) v2(48.26,26.67) v2(48.26,25.4) v2(48.26,24.13) v2(48.26,22.86) v2(48.51,46.35) v2(48.51,45.72) v2(48.51,45.09) v2(48.51,44.45) v2(48.51,39.37) v2(48.51,38.1) v2(48.51,36.83) v2(48.51,35.56) v2(48.51,34.29) v2(48.51,33.02) v2(48.51,31.75) v2(48.51,30.48) v2(48.51,29.21) v2(49.15,46.35) v2(49.15,45.72) v2(49.15,45.09) v2(49.15,44.45) v2(49.53,43.18) v2(49.53,41.91) v2(49.53,40.64) v2(49.53,39.37) v2(49.53,38.1) v2(49.53,36.83) v2(49.53,35.56) v2(49.53,34.29) v2(49.53,33.02) v2(49.53,31.75) v2(49.53,30.48) v2(49.53,29.21) v2(49.53,27.94) v2(49.53,26.67) v2(49.53,25.4) v2(49.78,46.35) v2(49.78,45.72) v2(49.78,45.09) v2(49.78,44.45) v2(51.82,46.35) v2(51.82,45.72) v2(51.88,19.81) v2(52.07,43.18) v2(52.07,41.91) v2(52.07,40.64) v2(52.07,39.37) v2(52.07,38.1) v2(52.07,36.83) v2(52.07,35.56) v2(52.07,34.29) v2(52.07,33.02) v2(52.07,31.75) v2(52.07,30.48) v2(52.07,29.21) v2(52.07,27.94) v2(52.07,26.67) v2(52.07,25.4) v2(52.45,46.35) v2(52.45,45.72) v2(52.45,45.09) v2(52.51,19.81) v2(53.09,46.35) v2(53.09,45.72) v2(53.09,45.09) v2(53.09,44.45) v2(53.21,39.37) v2(53.21,38.1) v2(53.21,36.83) v2(53.21,35.56) v2(53.21,34.29) v2(53.21,33.02) v2(53.21,31.75) v2(53.21,30.48) v2(53.21,29.21) v2(53.34,43.18) v2(53.34,41.91) v2(53.34,40.64) v2(53.34,27.94) v2(53.34,26.67) v2(53.34,25.4) v2(53.34,24.13) v2(53.34,22.86) v2(54.23,39.37) v2(54.23,38.1) v2(54.23,36.83) v2(54.23,35.56) v2(54.23,34.29) v2(54.23,33.02) v2(54.23,31.75) v2(54.23,30.48) v2(54.23,29.21) v2(54.61,43.18) v2(54.61,41.91) v2(54.61,40.64) v2(54.61,27.94) v2(54.61,26.67) v2(54.61,25.4) v2(54.74,46.35) v2(54.74,45.72) v2(54.74,45.09) v2(54.74,44.45) v2(54.99,39.88) v2(54.99,39.24) v2(54.99,38.61) v2(54.99,37.97) v2(54.99,37.34) v2(54.99,36.7) v2(54.99,36.07) v2(54.99,35.43) v2(54.99,34.8) v2(54.99,34.16) v2(54.99,33.53) v2(54.99,32.89) v2(54.99,32.26) v2(54.99,31.62) v2(54.99,30.99) v2(54.99,30.35) v2(54.99,29.72) v2(55.37,46.35) v2(55.37,45.72) v2(55.37,45.09) v2(55.37,44.45) v2(55.5,21.84) v2(55.5,21.21) v2(55.5,20.57) v2(55.5,19.56) v2(55.5,18.92) v2(55.5,18.29) v2(55.63,39.88) v2(55.63,39.24) v2(55.63,38.61) v2(55.63,37.97) v2(55.63,37.34) v2(55.63,36.7) v2(55.63,36.07) v2(55.63,35.43) v2(55.63,34.8) v2(55.63,34.16) v2(55.63,33.53) v2(55.63,32.89) v2(55.63,32.26) v2(55.63,31.62) v2(55.63,30.99) v2(55.63,30.35) v2(55.63,29.72) v2(55.88,41.91) v2(55.88,40.64) v2(55.88,27.94) v2(55.88,26.67) v2(55.88,25.4) v2(56.01,47.62) v2(56.01,46.99) v2(56.01,46.35) v2(56.01,45.72) v2(56.01,45.09) v2(56.01,44.45) v2(56.01,43.81) v2(56.01,43.18) v2(56.26,39.88) v2(56.26,39.24) v2(56.26,38.61) v2(56.26,37.97) v2(56.26,37.34) v2(56.26,36.7) v2(56.26,36.07) v2(56.26,35.43) v2(56.26,34.8) v2(56.26,34.16) v2(56.26,33.53) v2(56.26,32.89) v2(56.26,32.26) v2(56.26,31.62) v2(56.26,30.99) v2(56.26,30.35) v2(56.26,29.72) v2(56.64,47.62) v2(56.64,46.99) v2(56.64,46.35) v2(56.64,45.72) v2(56.64,45.09) v2(56.64,44.45) v2(56.64,43.81) v2(56.64,43.18) v2(56.9,39.88) v2(56.9,39.24) v2(56.9,38.61) v2(56.9,37.97) v2(56.9,37.34) v2(56.9,36.7) v2(56.9,36.07) v2(56.9,35.43) v2(56.9,34.8) v2(56.9,34.16) v2(56.9,33.53) v2(56.9,32.89) v2(56.9,32.26) v2(56.9,31.62) v2(56.9,30.99) v2(56.9,30.35) v2(56.9,29.72) v2(57.15,41.91) v2(57.15,40.64) v2(57.15,27.94) v2(57.15,26.67) v2(57.15,25.4) v2(57.53,39.88) v2(57.53,39.24) v2(57.53,38.61) v2(57.53,37.97) v2(57.53,37.34) v2(57.53,36.7) v2(57.53,36.07) v2(57.53,35.43) v2(57.53,34.8) v2(57.53,34.16) v2(57.53,33.53) v2(57.53,32.89) v2(57.53,32.26) v2(57.53,31.62) v2(57.53,30.99) v2(57.53,30.35) v2(57.53,29.72) v2(58.42,36.83) v2(58.42,35.56) v2(58.42,34.29) v2(58.42,33.02) v2(58.42,31.75) v2(58.42,30.48) v2(58.42,29.21) v2(58.42,27.94) v2(58.42,26.67) v2(58.42,25.4) v2(61.02,25.79) v2(61.02,25.12) v2(61.02,24.43) v2(61.66,25.79) v2(61.66,25.12) v2(61.66,24.43) v2(62.29,25.79) v2(62.29,25.12) v2(62.29,24.43) v2(62.93,25.79) v2(62.93,25.12) v2(62.93,24.43) v2(66.04,29.21) v2(66.04,27.94) v2(66.04,26.67) v2(66.04,25.53) v2(66.17,21.97) v2(67.31,48.26) v2(67.31,46.99) v2(67.31,45.72) v2(67.31,44.45) v2(67.31,43.18) v2(67.31,41.91) v2(67.31,40.64) v2(67.31,39.37) v2(67.31,38.1) v2(67.31,36.83) v2(67.31,35.56) v2(67.31,34.29) v2(67.31,33.02) v2(67.31,31.75) v2(67.31,30.48) v2(67.31,29.21) v2(67.31,27.94) v2(67.31,26.67) v2(67.31,25.53) v2(68.58,48.26) v2(68.58,46.99) v2(68.58,45.72) v2(68.58,44.45) v2(68.58,43.18) v2(68.58,41.91) v2(68.58,40.64) v2(68.58,39.37) v2(68.58,38.1) v2(68.58,36.83) v2(68.58,35.56) v2(68.58,34.29) v2(68.58,33.02) v2(68.58,31.75) v2(68.58,30.48) v2(68.58,29.21) v2(68.58,27.94) v2(68.58,26.67) v2(68.58,25.53) v2(69.85,46.99) v2(69.85,45.72) v2(69.85,44.45) v2(69.85,43.18) v2(69.85,41.91) v2(69.85,40.64) v2(69.85,39.37) v2(69.85,38.1) v2(69.85,36.83) v2(69.85,35.56) v2(69.85,34.29) v2(69.85,33.02) v2(69.85,31.75) v2(69.85,30.48) v2(69.85,29.21) v2(69.85,27.94) v2(69.85,26.67) v2(69.85,25.53) v2(71.12,46.99) v2(71.12,45.72) v2(71.12,44.45) v2(71.12,43.18) v2(71.12,41.91) v2(71.12,40.64) v2(71.12,39.37) v2(71.12,38.1) v2(71.12,36.83) v2(71.12,35.56) v2(71.12,34.29) v2(71.12,33.02) v2(71.12,31.75) v2(71.12,30.48) v2(71.12,29.21) v2(72.39,48.26) v2(72.39,46.99) v2(72.39,45.72) v2(72.39,45.09) v2(72.39,44.45) v2(72.39,43.81) v2(72.39,43.18) v2(72.39,42.55) v2(72.39,41.91) v2(72.39,41.27) v2(72.39,40.64) v2(72.39,40.01) v2(72.39,33.02) v2(72.39,31.75) v2(72.39,30.48) v2(72.52,54.74) v2(72.52,54.1) v2(72.52,53.47) v2(72.52,52.83) v2(72.52,52.2) v2(72.52,51.56) v2(72.52,50.93) v2(72.52,50.29) v2(72.52,49.66) v2(72.52,49.02) v2(73.15,54.74) v2(73.15,54.1) v2(73.15,53.47) v2(73.15,52.83) v2(73.15,52.2) v2(73.15,51.56) v2(73.15,50.93) v2(73.15,50.29) v2(73.15,49.66) v2(73.15,49.02)
VDD: length 85.1
  TOP w0.508: v2(62.1,23.37) 61.6,23.11 U1.8 ; J5.16 v1(21.59,14.73)
  LAYER3 w0.508: v1(43.43,17.27) 43.94,17.78 52.45,17.78 v1(53.09,17.14) ; v1(21.59,14.73) 21.59,13.21 20.45,12.06 20.45,9.53 21.08,8.89 37.21,8.89 39.5,6.6 46.1,6.6 E8.1
  LAYER6 w0.508: E8.1 49.53,7.87 53.34,11.68 53.34,16.89 v1(53.09,17.14) 55.76,17.14 58.67,20.07 59.19,20.07 62.1,22.99 v2(62.1,23.37)
  BOTTOM w0.508: v1(53.09,17.14) 52.41,17.14 52.2,17.36 C49.1 ; R21.2 43.47,17.24 v1(43.43,17.27) 42.2,17.27 R22.2 R20.2 R19.2 R18.2
VDDEXT: length 71.8
  TOP w0.254: 61.62,27.56 U1.10
  TOP w0.508: v2(62.1,27.56) 61.62,27.56 ; J5.15 21.62,10.38 v1(21.84,10.16)
  LAYER3 w0.508: E10.1 54.23,8.64 40.89,8.64 38.48,11.05 22.73,11.05 v1(21.84,10.16)
  LAYER6 w0.508: v2(62.1,27.56) 62.74,27.56 64.26,26.04 64.26,22.73 v2(63.88,22.35) 64.26,21.97 64.26,14.54 59.69,9.97 E10.1
VIN: length 41.8
  TOP w0.508: v1(28.45,15.88) 27.62,15.88 J5.22
  BOTTOM w0.254: v1(28.45,15.88) 28.83,15.49 31.24,15.49 34.42,12.32 55.75,12.32 57.53,14.1 57.53,22.23 57.72,22.42 v2(58.23,22.42)
  vias: v1(28.96,14.48) v1(28.96,13.84) v1(29.59,14.48) v1(29.59,13.84) v1(30.23,14.48) v1(30.23,13.84) v1(76.96,16.38) v1(76.96,15.11) v1(76.96,13.84) v1(79.25,16.38) v1(79.25,15.11) v1(79.25,13.84) v2(58.23,23.81) v2(58.23,23.11) v2(58.23,17.72) v2(58.23,17.08) v2(58.86,23.81) v2(58.86,23.11) v2(58.86,22.42) v2(58.86,17.72) v2(58.86,17.08) v2(59.5,23.81) v2(59.5,23.11) v2(59.5,22.42) v2(59.5,17.72) v2(59.5,17.08)
CTRL: length 47.6
  TOP w0.254: U1.3 v2(44.2,20.19)
  TOP w0.508: J5.11 v1(17.62,10.19)
  LAYER3 w0.254: v1(17.62,10.19) 20.19,7.62 34.92,7.62 E6.1
  LAYER6 w0.254: E6.1 39.37,15.37 v2(44.2,20.19)
  BOTTOM w0.254: R21.1 v2(44.2,20.19)
ISHARE: length 45.8
  TOP w0.254: U1.2 v2(42.16,20.19)
  TOP w0.508: J5.9 v1(15.62,10.16)
  LAYER3 w0.254: E5.1 30.86,6.6 19.18,6.6 v1(15.62,10.16)
  LAYER6 w0.254: E5.1 37.97,6.86 37.97,16 v2(42.16,20.19)
  BOTTOM w0.254: v2(42.16,20.19) 42.15,18.59 R22.1
LOADGATE: length 237
  TOP w0.254: v1(69.22,58.55) 69.22,58.07 R4.1 ; R1.1 32.26,58.2 v1(32.26,58.67)
  TOP w0.508: J5.6 v1(11.62,18.48)
  LAYER6 w0.254: v1(11.62,18.48) 11.62,38.67 13.08,40.13 13.08,49.02 9.14,52.96 9.14,63.37 19.3,73.53 27.9,73.53 32.26,69.18 32.26,62.36 29.21,59.31 29.21,58.17 29.97,57.4 31.24,57.4 32.26,58.42 v1(32.26,58.67) 32.26,59.27 34.29,61.3 34.29,69.22 37.72,72.64 63.88,72.64 67.31,69.22 67.31,61.05 69.22,59.14 v1(69.22,58.55) 69.22,58.04 69.72,57.53 71.88,57.53 72.9,58.55 72.9,69.98 77.09,74.17 82.55,74.17 99.82,56.9 99.82,36.96 E11.1
  BOTTOM w0.254: R4.1 69.22,58.07 v1(69.22,58.55) ; R1.1 32.26,58.2 v1(32.26,58.67) ; E11.1 R27.1
RSENSE+: length 157.7
  TOP w0.254: R7.2 v1(31.37,58.67) ; v1(70.1,58.55) R6.2
  TOP w0.508: J5.4 v1(9.59,18.48)
  LAYER6 w0.254: v1(70.1,58.55) 70.1,58.97 67.82,61.26 67.82,69.43 64.09,73.15 37.51,73.15 33.78,69.43 33.78,61.51 31.37,59.1 v1(31.37,58.67) 31.37,58.29 31.06,57.99 30.2,57.99 29.79,58.39 29.79,59.17 32.77,62.15 32.77,69.39 28.11,74.04 19.09,74.04 8.64,63.58 8.64,52.58 9.78,51.44 9.78,42.04 J2.1 9.4,39.62 9.4,18.67 v1(9.59,18.48)
  BOTTOM w0.254: R7.2 v1(31.37,58.67) ; v1(70.1,58.55) R6.2
RSENSE-: length 148.3
  TOP w0.254: R14.2 70.99,58.07 v1(70.99,58.55) ; R15.2 30.48,58.2 v1(30.48,58.67)
  TOP w0.508: J5.2 v1(7.62,18.48)
  LAYER6 w0.254: v1(7.62,18.48) 8.38,19.24 8.38,38.35 J2.3 6.73,42.04 6.73,51.18 8.13,52.58 8.13,63.79 18.88,74.55 28.32,74.55 33.27,69.6 ; 33.27,69.6 33.27,61.72 30.48,58.93 v1(30.48,58.67) ; 33.27,69.6 33.27,69.64 37.3,73.66 64.3,73.66 68.33,69.64 68.33,61.47 70.99,58.8 v1(70.99,58.55)
  BOTTOM w0.254: R14.2 70.99,58.07 v1(70.99,58.55) ; R15.2 30.48,58.2 v1(30.48,58.67)
SCL: length 55.5
  TOP w0.254: v2(39.5,24.26) 39.69,24 40,24.32 U1.20
  TOP w0.508: J5.5 v1(11.62,10.22)
  LAYER6 w0.254: v2(39.5,24.26) 38.99,23.75 38.1,23.75 33.4,19.05 33.4,13.21 27.69,7.49 18.29,7.49 J4.3 13.97,4.45 10.92,7.49 10.92,9.53 v1(11.62,10.22)
  BOTTOM w0.254: v2(39.5,24.26) 39.37,24.26 37.97,22.86 37.97,19.59 37.59,19.21 R18.1
SDA: length 56.5
  TOP w0.254: U1.21 39.57,22.86 v2(39.5,22.61)
  TOP w0.508: J5.3 9.62,10.26 v1(9.65,10.22)
  LAYER6 w0.254: v2(39.5,22.61) 38.99,23.11 38.18,23.11 33.91,18.84 33.91,13 27.9,6.99 18.54,6.99 16.51,4.95 J4.2 15.24,1.91 13.44,1.91 12.7,2.65 12.7,4.83 10.29,7.24 10.29,9.59 v1(9.65,10.22)
  BOTTOM w0.254: v2(39.5,22.61) 38.73,21.84 38.73,18.7 R19.1
SMBALERT: length 43.9
  TOP w0.254: v2(40.13,20.19) 40,20.33 U1.1
  TOP w0.508: J5.7 v1(13.59,10.16)
  LAYER3 w0.254: v1(13.59,10.16) 18.16,5.59 26.8,5.59 E4.1
  LAYER6 w0.254: E4.1 36.45,10.41 36.45,16.51 v2(40.13,20.19)
  BOTTOM w0.254: v2(40.13,20.19) R20.1
SYNC: length 80.7
  TOP w0.254: U1.7 61.62,20.45 v2(62.74,20.45)
  TOP w0.508: J5.1 v1(7.62,10.22)
  LAYER6 w0.254: v1(7.62,10.22) 9.08,8.76 9.08,2.73 10.67,1.14 22.1,1.14 E3.1 26.54,0.76 50.55,0.76 52.07,2.29 52.07,6.64 61.59,16.1 61.59,19.3 v2(62.74,20.45)
  BOTTOM w0.508: v2(62.74,20.45) 63.47,20.45 R26.1
VOUT: length 175.3
  TOP w0.127: 42.9,46.51 42.9,46.58 43.18,46.86 ; 42.9,46.51 42.9,45.95 ; 42.9,46.51 42.55,46.86 ; 42.9,45.95 43.18,46.23 ; 42.9,45.95 42.9,45.34 ; 59.05,46.86 58.7,46.51 58.7,46.58 58.42,46.86
  TOP w0.254: U1.11 v2(61.72,31.11)
  TOP w0.508: J5.12 v1(17.62,18.51)
  LAYER3 w0.254: v1(17.62,18.51) 18.54,19.43 30.1,19.43 35.94,13.59 v1(48.2,13.59)
  LAYER5 w0.254: v1(48.2,13.59) 48.51,13.91 48.51,14.82 49.02,15.32 49.02,21.97 50.8,23.75 v2(50.8,48.64)
  LAYER5 w0.508: v2(50.8,48.64) 50.8,72.64 53.21,75.06 83.82,75.06 86.49,72.39 v1(86.49,50.8)
  LAYER6 w0.254: E7.1 44.45,9.84 v1(48.2,13.59)
  BOTTOM w0.127: 42.9,46.51 42.9,46.58 43.18,46.86 ; 42.9,46.51 42.55,46.86 ; 42.9,46.51 42.9,45.95 ; 42.9,45.34 42.9,45.95 ; 42.9,45.95 43.18,46.23 ; 58.42,46.86 58.7,46.58 58.7,46.51 59.05,46.86
  BOTTOM w0.508: RSP.2 v1(48.2,13.59) ; R17.1 v1(86.49,50.8)
  vias: v2(35.56,54.23) v2(35.56,53.59) v2(35.56,52.96) v2(35.56,52.32) v2(35.56,51.69) v2(35.56,51.05) v2(36.2,54.23) v2(36.2,53.59) v2(36.2,52.96) v2(36.2,52.32) v2(36.2,51.69) v2(36.2,51.05) v2(36.83,54.23) v2(36.83,53.59) v2(36.83,52.96) v2(36.83,52.32) v2(36.83,51.69) v2(36.83,51.05) v2(37.47,54.23) v2(37.47,53.59) v2(37.47,52.96) v2(37.47,52.32) v2(37.47,51.69) v2(37.47,51.05) v2(37.97,38.99) v2(37.97,38.35) v2(37.97,37.72) v2(37.97,35.43) v2(37.97,34.8) v2(37.97,34.16) v2(37.97,31.75) v2(37.97,31.11) v2(37.97,30.48) v2(38.1,54.23) v2(38.1,53.59) v2(38.1,52.96) v2(38.1,52.32) v2(38.1,51.69) v2(38.1,51.05) v2(38.61,38.99) v2(38.6,38.35) v2(38.61,37.72) v2(38.61,35.43) v2(38.6,34.79) v2(38.61,34.16) v2(38.61,31.75) v2(38.6,31.11) v2(38.61,30.48) v2(38.73,54.23) v2(38.73,53.59) v2(38.73,52.96) v2(38.73,52.32) v2(38.73,51.69) v2(38.73,51.05) v2(38.73,47.62) v2(38.73,46.86) v2(38.73,45.97) v2(38.73,45.21) v2(38.73,44.32) v2(38.73,43.56) v2(39.24,38.99) v2(39.24,38.35) v2(39.24,37.72) v2(39.24,35.43) v2(39.24,34.79) v2(39.24,34.16) v2(39.24,31.75) v2(39.24,31.11) v2(39.24,30.48) v2(39.37,54.23) v2(39.37,53.59) v2(39.37,52.96) v2(39.37,52.32) v2(39.37,51.69) v2(39.37,51.05) v2(39.88,38.99) v2(39.87,38.35) v2(39.88,37.72) v2(39.88,35.43) v2(39.87,34.79) v2(39.88,34.16) v2(39.88,31.75) v2(39.87,31.11) v2(39.88,30.48) v2(40.51,47.62) v2(40.51,46.86) v2(40.51,45.97) v2(40.51,45.21) v2(40.51,44.32) v2(40.51,43.56) v2(40.51,38.99) v2(40.51,38.35) v2(40.51,37.72) v2(40.51,35.43) v2(40.51,34.79) v2(40.51,34.16) v2(40.51,31.75) v2(40.51,31.11) v2(40.51,30.48) v2(41.91,46.61) v2(41.91,45.97) v2(41.91,45.34) v2(41.91,44.7) v2(41.91,44.07) v2(42.55,46.61) v2(42.55,45.97) v2(42.55,45.34) v2(42.55,44.7) v2(42.55,44.07) v2(43.18,46.61) v2(43.18,45.97) v2(43.18,45.34) v2(43.18,44.7) v2(43.18,44.07) v2(43.81,46.61) v2(43.81,45.97) v2(43.81,45.34) v2(43.81,44.7) v2(43.81,44.07) v2(57.78,46.61) v2(57.78,45.97) v2(57.78,45.34) v2(57.78,44.7) v2(57.78,44.07) v2(58.42,46.61) v2(58.42,45.97) v2(58.42,45.34) v2(58.42,44.7) v2(58.42,44.07) v2(59.05,46.61) v2(59.05,45.97) v2(59.05,45.34) v2(59.05,44.7) v2(59.05,44.07) v2(59.69,46.61) v2(59.69,45.97) v2(59.69,45.34) v2(59.69,44.7) v2(59.69,44.07) v2(61.09,39.12) v2(61.08,38.48) v2(61.09,37.85) v2(61.09,35.43) v2(61.08,34.79) v2(61.09,34.16) v2(61.09,31.75) v2(61.08,31.11) v2(61.09,30.48) v2(61.21,47.5) v2(61.21,46.74) v2(61.21,45.85) v2(61.21,45.09) v2(61.21,44.2) v2(61.21,43.43) v2(61.72,39.12) v2(61.72,38.48) v2(61.72,37.85) v2(61.72,35.43) v2(61.72,34.79) v2(61.72,34.16) v2(61.72,31.75) v2(61.72,30.48) v2(62.36,54.1) v2(62.36,53.47) v2(62.36,52.83) v2(62.36,52.2) v2(62.36,51.56) v2(62.36,50.93) v2(62.36,39.12) v2(62.35,38.48) v2(62.36,37.85) v2(62.36,35.43) v2(62.35,34.79) v2(62.36,34.16) v2(62.36,31.75) v2(62.35,31.11) v2(62.36,30.48) v2(62.99,54.1) v2(62.99,53.47) v2(62.99,52.83) v2(62.99,52.2) v2(62.99,51.56) v2(62.99,50.93) v2(62.99,47.5) v2(62.99,46.74) v2(62.99,45.85) v2(62.99,45.09) v2(62.99,44.2) v2(62.99,43.43) v2(62.99,39.12) v2(62.99,38.48) v2(62.99,37.85) v2(62.99,35.43) v2(62.99,34.79) v2(62.99,34.16) v2(62.99,31.75) v2(62.99,31.11) v2(62.99,30.48) v2(63.63,54.1) v2(63.63,53.47) v2(63.63,52.83) v2(63.63,52.2) v2(63.63,51.56) v2(63.63,50.93) v2(63.63,39.12) v2(63.63,38.48) v2(63.63,37.85) v2(63.63,35.43) v2(63.63,34.8) v2(63.63,34.16) v2(63.63,31.75) v2(63.63,31.11) v2(63.63,30.48) v2(64.26,54.1) v2(64.26,53.47) v2(64.26,52.83) v2(64.26,52.2) v2(64.26,51.56) v2(64.26,50.93) v2(64.9,54.1) v2(64.9,53.47) v2(64.9,52.83) v2(64.9,52.2) v2(64.9,51.56) v2(64.9,50.93) v2(65.53,54.1) v2(65.53,53.47) v2(65.53,52.83) v2(65.53,52.2) v2(65.53,51.56) v2(65.53,50.93) v2(66.17,54.1) v2(66.17,53.47) v2(66.17,52.83) v2(66.17,52.2) v2(66.17,51.56) v2(66.17,50.93)
N17349827: length 10.3
  TOP w0.254: R6.1 70.1,56.26 70.54,55.82 70.54,55.82 70.77,55.59 70.9,55.59 71.12,55.37 71.12,52.2 70.87,51.94 R10.1 68.26,51.94 M4.2 ; M4.2 M4.1 ; M4.2 M4.3
N17349858: length 10
  TOP w0.254: R7.1 30.61,55.59 30.61,52.39 30.92,52.07 R11.1 31.9,51.94 M1.3 M1.2 M1.1
N17349901: length 5.8
  BOTTOM w0.254: R5.1 70.23,56.23 70.23,56.13 71.12,55.24 71.12,52.32 70.74,51.94 R9.1
N17354471: length 2.4
  TOP w0.254: M4.4 68.33,54.36 68.58,54.61 68.58,56.1 R4.2
N17359340: length 9.8
  BOTTOM w0.508: J1.1 J2.2
N17393939: length 2.4
  TOP w0.254: v2(45.97,20.19) 45.85,20.32 46.14,20.61 U1.4
  BOTTOM w0.254: v2(45.97,20.19) 45.59,19.81 R25.1
N17425885: length 5.6
  BOTTOM w0.254: R8.1 31.37,56.26 30.61,55.5 30.61,52.39 30.92,52.07 R12.1
N17521903: length 48.6
  LAYER3 w0.254: v1(94.23,22.61) 93.85,22.99 93.34,22.99 91.69,21.34 75.06,21.34 67.94,14.22 51.94,14.22 51.82,14.1 51.82,13.72 v1(52.01,13.53)
  BOTTOM w0.254: RFF.2 v1(52.01,13.53) ; R38.1 v1(94.23,22.61)
N17521912: length 49.5
  LAYER3 w0.254: v1(94.23,23.88) 93.85,23.5 93.09,23.5 91.44,21.84 74.8,21.84 67.69,14.73 51.69,14.73 50.93,13.97 50.93,13.84 v1(50.67,13.59)
  BOTTOM w0.254: R37.2 v1(50.67,13.59) ; R39.1 v1(94.23,23.88)
N17523958: length 4.7
  TOP w0.254: U1.6 50.15,20.34 v2(50.29,20.19) 50.29,17.87 CVS.1
  BOTTOM w0.254: R33.2 50.67,19.81 v2(50.29,20.19)
N17523961: length 7.7
  TOP w0.254: v2(48.13,20.19) U1.5 48.15,18.49 CVS.2
  BOTTOM w0.254: CFF.1 R32.1 ; CFF.1 R31.1 ; CFF.1 v2(48.13,20.19)
N17524029: length 5.7
  BOTTOM w0.254: R37.1 R33.1 R32.2 RSN.1 R37.1
N17524083: length 4.1
  BOTTOM w0.508: R31.2 46.86,15.66 R34.1 RSP.1 D1.1
N17524971: length 6.2
  LAYER3 w0.254: v1(48.13,16.38) 48.2,16.32 v1(51.94,16.32)
  BOTTOM w0.254: v1(51.94,16.32) 52.01,16.26 RFF.1 ; CFF.2 v1(48.13,16.38) 48.13,15.66 R34.2 48.14,15.62
N173357071: length 4.8
  BOTTOM w0.508: J3.1 R17.2
N173562991: length 7.9
  TOP w0.254: R1.2 33.69,56.35 34.67,55.37 34.67,50.92 34.42,50.67 M1.4
N173563321: length 7.9
  BOTTOM w0.254: R2.2 68.8,56.35 68.2,55.75 67.44,55.75 67.06,55.37 67.06,50.79 67.3,50.55 M2.4
N174258781: length 2.4
  BOTTOM w0.254: R3.2 33.15,55.97 33.15,54.61 33.27,54.48 M3.4
N175287170: length 2.9
  BOTTOM w0.254: R38.2 96.43,19.78 E13.1 96.53,19.69
N175287240: length 2.8
  BOTTOM w0.254: R39.2 96.43,26.58 E14.1 96.53,26.66

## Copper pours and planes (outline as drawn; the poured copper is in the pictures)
GND on TOP: outline of 85 points within 0.64,0.51 100.96,75.56 ; 1 cut-out
GND on BOTTOM: outline of 90 points within 0.64,0.51 100.96,75.56 ; 1 cut-out
GND on LAYER2: 0.64,75.56 100.96,75.56 100.96,0.51 0.64,0.51 ; 11 cut-outs
GND on LAYER3: 0.64,75.56 100.96,75.56 100.96,0.51 0.64,0.51 ; 1 cut-out
GND on LAYER4: 0.64,75.56 100.96,75.56 100.96,0.51 0.64,0.51 ; 11 cut-outs
GND on LAYER5: 0.64,75.56 100.96,75.56 100.96,0.51 0.64,0.51 ; 12 cut-outs
GND on LAYER6: 0.64,75.56 100.96,75.56 100.96,0.51 0.64,0.51 ; 1 cut-out
GND on LAYER7: 0.64,75.56 100.96,75.56 100.96,0.51 0.64,0.51 ; 11 cut-outs
VIN on TOP: 56.64,24.13 59.82,24.13 59.82,19.05 59.83,19 59.85,18.96 61.89,16.93 61.93,16.9 61.98,16.89 89.74,16.89 92.46,14.17 92.46,0.51 81.66,0.51 81.66,9.14 81.65,9.19 81.62,9.23 80.23,10.63 80.19,10.66 80.14,10.67 61.65,10.67 56.64,15.67
VIN on TOP: 26.8,18.29 30.61,18.29 30.61,10.41 26.8,10.41
VIN on BOTTOM: 57.91,24.13 59.64,24.13 61.47,22.3 61.47,17.02 61.51,16.93 61.59,16.89 89.74,16.89 92.46,14.17 92.46,0.51 81.66,0.51 81.66,10.54 81.62,10.63 81.53,10.67 61.59,10.67 61.55,10.66 61.51,10.63 59.26,8.38 33.07,8.38 28.07,13.39 28.07,15.11 31.06,15.11 34.2,11.98 34.24,11.95 34.29,11.94 55.88,11.94 55.93,11.95 55.97,11.98 57.87,13.88 57.9,13.92 57.91,13.97
VIN on LAYER2, LAYER5: 57.91,24.13 59.82,24.13 59.82,22.1 57.91,22.1
VIN on LAYER4, LAYER7: 57.78,24.13 59.82,24.13 59.82,22.1 57.78,22.1
VOUT on TOP: 34.92,75.56 66.67,75.56 66.67,31.68 64.33,29.36 60.81,29.34 57.4,43.71 57.4,43.72 57.4,48.13 57.37,48.22 57.28,48.26 44.32,48.26 44.23,48.22 44.2,48.13 44.19,43.84 44.2,43.83 40.79,29.34 37.39,29.36 34.92,31.83 34.92,50.02 34.92,50.05 34.92,55.61 34.92,55.64
VOUT on BOTTOM: 34.92,75.56 66.67,75.56 66.67,31.93 64.33,29.34 59.44,29.34 59.44,41.66 59.43,41.7 59.4,41.75 57.4,43.74 57.4,48.13 57.37,48.22 57.28,48.26 44.32,48.26 44.23,48.22 44.2,48.13 44.2,43.87 42.2,41.87 42.17,41.83 42.16,41.78 42.16,29.34 37.39,29.34 34.92,31.8
VOUT on LAYER2: 60.77,32.07 64.07,32.07 64.07,30.16 60.77,30.16
VOUT on LAYER2: 37.59,39.31 40.89,39.31 40.89,37.4 37.59,37.4
VOUT on LAYER2: 60.71,39.43 64.01,39.43 64.01,37.53 60.71,37.53
VOUT on LAYER2: 37.59,32.07 40.89,32.07 40.89,30.16 37.59,30.16
VOUT on LAYER2: 37.59,35.75 40.89,35.75 40.89,33.85 37.59,33.85
VOUT on LAYER2: 60.71,35.75 64.01,35.75 64.01,33.85 60.71,33.85
VOUT on LAYER2, LAYER4, LAYER5, LAYER7: 41.53,46.99 44.2,46.99 44.2,43.69 41.53,43.69
VOUT on LAYER2, LAYER5: 61.98,54.48 66.55,54.48 66.55,50.55 61.98,50.55
VOUT on LAYER2, LAYER5: 35.24,54.66 39.81,54.66 39.81,50.73 35.24,50.73
VOUT on LAYER2, LAYER5: 57.4,46.99 60.07,46.99 60.07,43.69 57.4,43.69
VOUT on LAYER3: 37.9,72.01 63.57,72.01 66.67,68.91 66.67,31.68 64.33,29.36 60.81,29.34 57.4,43.71 57.4,43.72 57.4,48.13 57.37,48.22 57.28,48.26 44.32,48.26 44.23,48.22 44.2,48.13 44.19,43.84 44.2,43.83 40.79,29.34 37.39,29.36 34.92,31.83 34.92,69.04
VOUT on LAYER4: 37.66,39.31 40.89,39.31 40.89,37.4 37.66,37.4
VOUT on LAYER4: 37.66,35.75 40.89,35.75 40.89,33.85 37.66,33.85
VOUT on LAYER4: 60.77,32.07 64.01,32.07 64.01,30.16 60.77,30.16
VOUT on LAYER4: 60.77,39.43 64.01,39.43 64.01,37.53 60.77,37.53
VOUT on LAYER4: 60.77,35.75 64.01,35.75 64.01,33.85 60.77,33.85
VOUT on LAYER4: 37.66,32.07 40.89,32.07 40.89,30.16 37.66,30.16
VOUT on LAYER4, LAYER7: 35.18,54.61 39.75,54.61 39.73,50.7 35.18,50.67
VOUT on LAYER4, LAYER7: 61.95,54.51 66.52,54.51 66.5,50.59 61.95,50.57
VOUT on LAYER4, LAYER7: 57.41,46.93 60.07,46.93 60.07,43.63 57.41,43.63
VOUT on LAYER5, LAYER7: 60.77,39.43 63.94,39.43 63.94,37.53 60.77,37.53
VOUT on LAYER5, LAYER7: 37.66,35.75 40.83,35.75 40.83,33.85 37.66,33.85
VOUT on LAYER5, LAYER7: 37.66,32.07 40.83,32.07 40.83,30.16 37.66,30.16
VOUT on LAYER5, LAYER7: 60.77,35.75 63.94,35.75 63.94,33.85 60.77,33.85
VOUT on LAYER5, LAYER7: 60.77,32.07 63.94,32.07 63.94,30.16 60.77,30.16
VOUT on LAYER5, LAYER7: 37.66,39.31 40.83,39.31 40.83,37.4 37.66,37.4
VOUT on LAYER6: 37.9,72.01 63.57,72.01 66.67,68.91 66.67,31.68 64.34,29.34 60.81,29.34 57.4,43.7 57.4,48.13 57.37,48.22 57.28,48.26 44.32,48.26 44.23,48.22 44.2,48.13 44.2,43.83 40.79,29.34 37.39,29.34 34.92,31.8 34.92,69.04
N17349827 on TOP: 68.71,55.37 70.43,55.37 70.61,55.19 70.61,51.69 70.65,51.6 70.74,51.56 71.25,51.56 71.25,48.64 69.22,48.64 69.22,49.78 69.18,49.87 69.09,49.91 66.93,49.91 66.93,53.72 68.71,53.72
N17349858 on TOP: 31.11,55.5 34.67,55.5 34.67,50.16 32.77,50.16 32.68,50.13 32.64,50.04 32.64,48.77 30.48,48.77 30.48,51.69 30.99,51.69 31.08,51.73 31.11,51.82
N17349901 on BOTTOM: 67.44,55.37 70.43,55.37 70.61,55.19 70.61,51.69 71.25,51.69 71.25,48.64 69.22,48.64 69.22,51.18 69.18,51.27 69.09,51.31 67.44,51.31
N17425885 on BOTTOM: 31.11,55.37 33.02,55.37 33.02,53.85 34.67,53.85 34.67,50.04 32.64,50.04 32.55,50 32.51,49.91 32.51,48.77 30.48,48.77 30.48,51.69 31.11,51.69

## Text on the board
BOTTOM: REV1 | LAYER 8 - BOTTOM LAYER
Ref Des/Silkscreen Bottom: www.analog.com | FOR CUSTOMER USE ONLY | BOTTOM SILKSCREEN
TOP: LAYER 1 - TOP LAYER
Ref Des/Silkscreen Top: R- | R+ | TOP SILKSCREEN | SYNC | SMB | See Demo Manual | REMOTE_VOUT- | REMOTE_VOUT+ | 40V ~ 65V | GATE | GND | ISHARE | CTRL | VOUTS | 3V3 | BIAS | 54V INPUT HIGH CURRENT | WITH PMBUS INTERFACE | DC/DC POWER MODULE | DC3190A- | VOUT | VIN | LTP88
LAYER2: LAYER 2 - GND
LAYER3: LAYER 3 - SIGNAL
LAYER4: LAYER 4 - GND
LAYER5: LAYER 5 - SIGNAL
LAYER6: LAYER 6 - SIGNAL
LAYER7: LAYER 7 - GND
DEVICE_TYPE_TOP: ANALOG DEVICES | DC3190A-*, LTP88XX | DATE: 11-18-21
DIMENSION: TM | NUT, BRASS, #10-32 | PCB | INSTALL STUD | BOTTOM SIDE | TOP SIDE | (FACE RING LUG AT EDGE OF THE BOARD) | (PRESS FIT AND SOLDER, THIS SIDE) | STUD, PRESS-FIT, KFH-032-6 | WASHER, LOCK, #10 | LUG, RING, #10 | 5. | 6. | 7. | 1. WORKMANSHIP SHALL BE IN ACCORDANCE WITH IPC-A-610. | 2. ASSEMBLY PROCESS SHALL INCLUDE: REFLOW SOLDER TOP SIDE SMD. | 3. PARTS TO OMIT WILL BE SPECIFIED ON THE BILL OF MATERIALS. | 4. INSTALL SHUNTS AS SHOWN ON ASSY DRAWING. | SOLDER | MAXIMUM SOLDER TEMPERATURE IS 240 DEG C. | LOCATIONS OF OMITTED PARTS SHALL BE FREE OF SOLDER. | MASK THE SOLDER STENCIL WHERE SMT PARTS ARE OMITTED. | DEPANELIZE BOARDS AFTER ASSEMBLY AND ROUTE-OUT THE | BREAKOUT TABS ON FOUR SIDES OF THE BOARD EDGE. | DO NOT APPLY ANY KIND OF ASSEMBLY STAMP OR QA STAMP | TO ANY BOARD. | INSTALL 4 STANDOFFS AT 4 LOCATIONS AS SHOWN BELOW: | TITLE: | SIZE | www.analog.com | TOP ASSEMBLY DRAWING | IC NO. | TURRETS | PCB : TOP | PCB : BOTTOM | 4X STANDOFF, NYLON, SNAP ON. | FOR ADI CUSTOMER USE ONLY | SHT 1 OF 2 | REV. | N/A | J6-J9 | BANANA JACK : KEYSTONE 575-4 | 54 V INPUT, HIGH CURRENT DC/DC | POWER MODULE WITH PMBUS INTERFACE | LTP88xx | DC3190A | 5 | IMPORTANT: MARK EACH VERISON PER BOM | IN THE SQUARES ABOVE AND MARK U1 PER BOM
ASSEMBLY_BOTTOM: TM | 5 | REV | SHT 2 of 2 | FOR ADI CUSTOMER USE ONLY | IC NO. | BOTTOM ASSEMBLY DRAWING | www.analog.com | SIZE | TITLE: | N/A | Y | B | R | E | W | O | P | DC3190A | LTP88xx | POWER MODULE WITH PMBUS INTERFACE | 54V INPUT, HIGH CURRENT DC/DC
User.5: TOP SILKSCREEN
User.6: BOTTOM SILKSCREEN
User.7: TOP SOLDER MASK
User.8: BOTTOM SOLDER MASK
User.9: TOP PASTE MASK
User.10: BOTTOM PASTE MASK
